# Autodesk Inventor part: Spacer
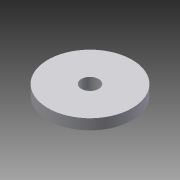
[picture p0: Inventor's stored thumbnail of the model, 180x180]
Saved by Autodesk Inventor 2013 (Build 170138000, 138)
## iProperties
Shininess: 9.0
Length Units: 11272
Angle Units: 11279
Time Units: 11290
Mass Units: 11286
Length Display Precision: 3
Angle Display Precision: 2
Compacted: True
Created: 2001-11
Part Number: Spacer
Document SubType Name: Modeling
Designer: Autodesk, Inc.
Mass: 0.788664 g
Surface Area: 8.16584 cm^2
Volume: 0.788664 cm^3
Density: 1 g/cm^3
Material: Generic
Density: 0.0
Volumn: 0.0
Area: 0.0
PropertySet Name: Model Information
Control State: 0
Master: False
Checked Out: False
Author: Autodesk, Inc.
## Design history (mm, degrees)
sketch "Sketch1"
  geometry: L1 (162.642, 127.182)-(154.578, 127.182); L2 (162.642, 129.722)-(162.642, 127.182); L3 (154.578, 129.722)-(162.642, 129.722); L4 (154.578, 127.182)-(154.578, 129.722); L5 (152.482, 125.089)-(152.482, 131.695); L6 (152.482, 125.089)-(152.482, 131.695)
  constraints: 12 end point, 3 vertical, 2 horizontal, 1 other
  dimensions: "d1" = 8.0645 distance of L3.start L2.start; "d2" = 2.0955 distance between parallel lines of L5 L4; "d3" = 2.54 distance of L2.start L1.start
revolve "RevolutionFull1" sketch "Sketch1" stored, may be unused: angle "d0" = 360 deg
body "Solid1"
